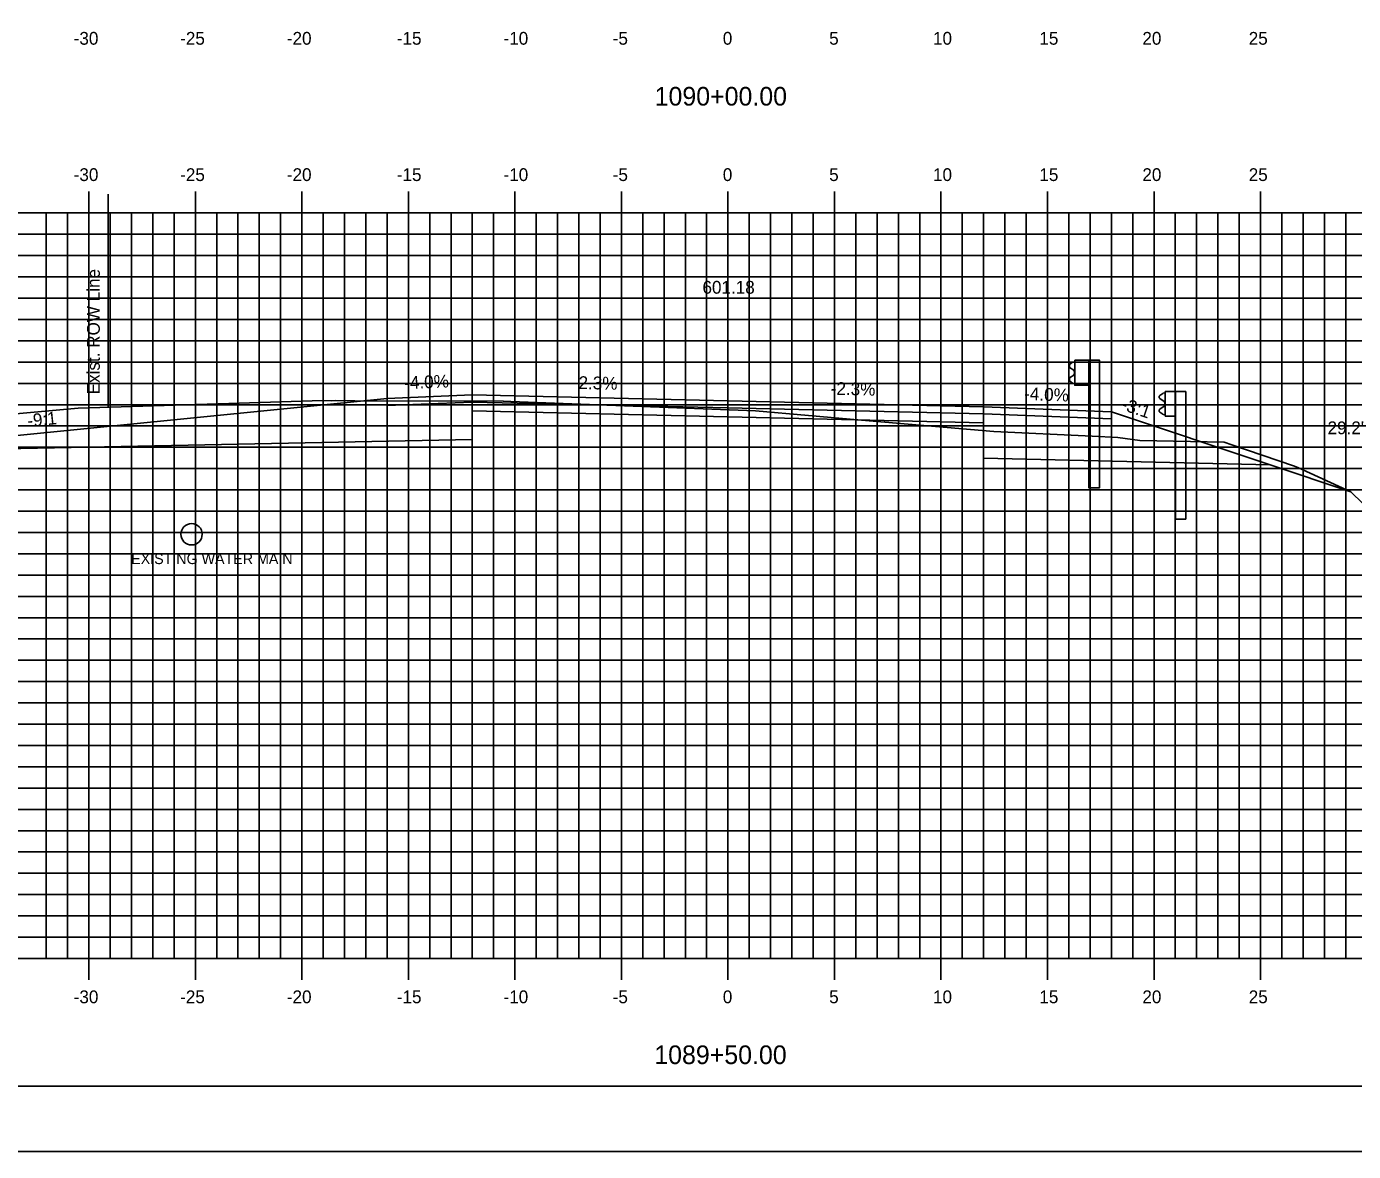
# Model space of a CAD drawing. Extents: x 1073421 to 1073591, y 779716 to 779826.
# Drawn here: x 1073471 to 1073533.3, y 779715.6 to 779768.5 of the extents above; entities that cross this region are included whole.
import ezdxf

# ---------------------------------------------------------------- set-up
doc = ezdxf.new("R2010")
doc.units = 0
for name, color, linetype in [('ANNOTATION', 7, 'Continuous'), ('BORDER', 7, 'Continuous'), ('D_Guardrail_Beam_Rt', 7, 'Continuous'), ('D_Roadway_Centerline', 7, 'Continuous'), ('D_Roadway_Centerline_Text', 7, 'Continuous'), ('D_Roadway_Edge_Pavement', 7, 'Continuous'), ('D_Roadway_Edge_Shoulder', 7, 'Continuous'), ('D_Roadway_Pavement', 7, 'Continuous'), ('D_Roadway_SlopeLines', 7, 'Continuous'), ('D_Roadway_SubGrade', 7, 'Continuous'), ('D_Text_Monospaced', 7, 'Continuous'), ('D_Text_Standard', 7, 'Continuous'), ('E_ROW_Line', 7, 'Continuous'), ('Existing Water Main', 7, 'Continuous'), ('H_V ANNOTATION', 7, 'Continuous'), ('M_Guardrail', 7, 'Continuous'), ('MAJOR', 7, 'Continuous'), ('MINOR', 7, 'Continuous'), ('PLOT BOUNDARY', 7, 'Continuous'), ('S_Guardrail_Beam', 7, 'Continuous'), ('S_Roadway_Centerline', 7, 'Continuous')]:
    doc.layers.add(name, color=color, linetype=linetype)

msp = doc.modelspace()

# ---------------------------------------------------------------- linework, layer by layer
at = {"layer": 'BORDER'}
msp.add_lwpolyline([(1073428.959, 779718.706), (1073588.959, 779718.706), (1073588.959, 779823.706), (1073428.959, 779823.706)], close=True, dxfattribs=at)
at = {"layer": 'D_Guardrail_Beam_Rt'}
msp.add_lwpolyline([(1073520.238, 779752.721), (1073520.156, 779752.706), (1073520.139, 779752.699), (1073519.996, 779752.599), (1073519.996, 779752.456), (1073520.191, 779752.319), (1073520.225, 779752.255), (1073520.225, 779752.164), (1073520.191, 779752.099), (1073519.996, 779751.963), (1073519.996, 779751.819), (1073520.139, 779751.719), (1073520.156, 779751.712), (1073520.238, 779751.698)], dxfattribs=at)
for points in [[(1073520.238, 779752.8), (1073520.904, 779752.8), (1073520.904, 779751.619), (1073520.238, 779751.619)], [(1073520.904, 779752.8), (1073521.397, 779752.8), (1073521.397, 779746.796), (1073520.904, 779746.796)]]:
    msp.add_lwpolyline(points, close=True, dxfattribs=at)
at = {"layer": 'D_Roadway_Centerline'}
for points in [[(1073487.959, 779751.001), (1073491.959, 779751.161), (1073503.959, 779750.885), (1073515.959, 779750.609), (1073519.959, 779750.449), (1073521.959, 779750.369)], [(1073529.418, 779747.882), (1073533.205, 779746.62)]]:
    msp.add_lwpolyline(points, dxfattribs=at)
at = {"layer": 'D_Roadway_Edge_Pavement'}
msp.add_lwpolyline([(1073491.959, 779750.827), (1073491.959, 779751.161), (1073503.959, 779750.885), (1073515.959, 779750.609), (1073515.959, 779750.275), (1073503.959, 779750.551)], close=True, dxfattribs=at)
at = {"layer": 'D_Roadway_Edge_Shoulder'}
msp.add_lwpolyline([(1073491.959, 779751.161), (1073487.959, 779751.001), (1073487.959, 779750.667), (1073491.959, 779750.827)], close=True, dxfattribs=at)
msp.add_lwpolyline([(1073515.959, 779750.609), (1073519.959, 779750.449), (1073521.959, 779750.369), (1073521.959, 779750.035), (1073515.959, 779750.275), (1073515.959, 779750.609)], dxfattribs=at)
at = {"layer": 'D_Roadway_Pavement'}
msp.add_lwpolyline([(1073491.959, 779750.411), (1073491.959, 779750.827), (1073503.959, 779750.551), (1073515.959, 779750.275), (1073515.959, 779749.859), (1073503.959, 779750.135)], close=True, dxfattribs=at)
msp.add_lwpolyline([(1073491.959, 779750.827), (1073491.959, 779750.411)], dxfattribs=at)
at = {"layer": 'D_Roadway_SlopeLines'}
for points in [[(1073491.959, 779751.161), (1073487.959, 779751.001)], [(1073521.959, 779750.369), (1073529.418, 779747.882), (1073533.205, 779746.62)]]:
    msp.add_lwpolyline(points, dxfattribs=at)
at = {"layer": 'D_Roadway_SubGrade'}
msp.add_lwpolyline([(1073491.959, 779750.827), (1073487.959, 779750.667), (1073487.959, 779751.001), (1073462.918, 779748.496), (1073491.959, 779749.077), (1073491.959, 779750.827)], close=True, dxfattribs=at)
msp.add_lwpolyline([(1073529.418, 779747.882), (1073515.959, 779748.192), (1073515.959, 779748.775), (1073515.959, 779750.275), (1073515.959, 779750.275), (1073521.959, 779750.035), (1073521.959, 779750.369)], dxfattribs=at)
at = {"layer": 'E_ROW_Line'}
msp.add_line((1073474.873, 779750.592), (1073474.873, 779760.592), dxfattribs=at)
msp.add_line((1073474.873, 779750.592), (1073474.873, 779760.592), dxfattribs=at)
at = {"layer": 'Existing Water Main'}
msp.add_lwpolyline([(1073478.78, 779744.623), (1073478.779, 779744.623)], dxfattribs=at)
msp.add_circle((1073478.779, 779744.623), 0.501, dxfattribs=at)
at = {"layer": 'M_Guardrail'}
for p, q in [((1073524.967, 779751.331), (1073525.459, 779751.331)), ((1073525.459, 779751.331), (1073525.459, 779745.331)), ((1073524.967, 779745.331), (1073524.967, 779750.165)), ((1073524.967, 779745.331), (1073525.459, 779745.331))]:
    msp.add_line(p, q, dxfattribs=at)
at = {"layer": 'MAJOR'}
for p, q in [((1073473.959, 779760.708), (1073473.959, 779759.706)), ((1073478.959, 779760.708), (1073478.959, 779759.706)), ((1073483.959, 779760.708), (1073483.959, 779759.706)), ((1073488.959, 779760.708), (1073488.959, 779759.706)), ((1073493.959, 779760.708), (1073493.959, 779759.706)), ((1073498.959, 779760.708), (1073498.959, 779759.706)), ((1073503.959, 779760.708), (1073503.959, 779759.706)), ((1073508.959, 779760.708), (1073508.959, 779759.706)), ((1073513.959, 779760.708), (1073513.959, 779759.706)), ((1073518.959, 779760.708), (1073518.959, 779759.706)), ((1073523.959, 779760.708), (1073523.959, 779759.706)), ((1073528.959, 779760.708), (1073528.959, 779759.706)), ((1073433.959, 779759.706), (1073573.959, 779759.706)), ((1073433.959, 779759.706), (1073573.959, 779759.706)), ((1073473.959, 779724.706), (1073473.959, 779759.706)), ((1073478.959, 779724.706), (1073478.959, 779759.706)), ((1073483.959, 779724.706), (1073483.959, 779759.706)), ((1073488.959, 779724.706), (1073488.959, 779759.706)), ((1073493.959, 779724.706), (1073493.959, 779759.706)), ((1073498.959, 779724.706), (1073498.959, 779759.706)), ((1073503.959, 779724.706), (1073503.959, 779759.706)), ((1073508.959, 779724.706), (1073508.959, 779759.706)), ((1073513.959, 779724.706), (1073513.959, 779759.706)), ((1073518.959, 779724.706), (1073518.959, 779759.706)), ((1073523.959, 779724.706), (1073523.959, 779759.706)), ((1073528.959, 779724.706), (1073528.959, 779759.706)), ((1073433.959, 779754.706), (1073573.959, 779754.706)), ((1073433.959, 779749.706), (1073573.959, 779749.706)), ((1073433.959, 779744.706), (1073573.959, 779744.706)), ((1073433.959, 779739.706), (1073573.959, 779739.706)), ((1073433.959, 779734.706), (1073573.959, 779734.706)), ((1073433.959, 779729.706), (1073573.959, 779729.706)), ((1073433.959, 779724.706), (1073573.959, 779724.706)), ((1073433.959, 779724.706), (1073573.959, 779724.706)), ((1073473.959, 779723.704), (1073473.959, 779724.706)), ((1073478.959, 779723.704), (1073478.959, 779724.706)), ((1073483.959, 779723.704), (1073483.959, 779724.706)), ((1073488.959, 779723.704), (1073488.959, 779724.706)), ((1073493.959, 779723.704), (1073493.959, 779724.706)), ((1073498.959, 779723.704), (1073498.959, 779724.706)), ((1073503.959, 779723.704), (1073503.959, 779724.706)), ((1073508.959, 779723.704), (1073508.959, 779724.706)), ((1073513.959, 779723.704), (1073513.959, 779724.706)), ((1073518.959, 779723.704), (1073518.959, 779724.706)), ((1073523.959, 779723.704), (1073523.959, 779724.706)), ((1073528.959, 779723.704), (1073528.959, 779724.706))]:
    msp.add_line(p, q, dxfattribs=at)
at = {"layer": 'MINOR'}
for p, q in [((1073471.959, 779724.706), (1073471.959, 779759.706)), ((1073472.959, 779724.706), (1073472.959, 779759.706)), ((1073474.959, 779724.706), (1073474.959, 779759.706)), ((1073475.959, 779724.706), (1073475.959, 779759.706)), ((1073476.959, 779724.706), (1073476.959, 779759.706)), ((1073477.959, 779724.706), (1073477.959, 779759.706)), ((1073479.959, 779724.706), (1073479.959, 779759.706)), ((1073480.959, 779724.706), (1073480.959, 779759.706)), ((1073481.959, 779724.706), (1073481.959, 779759.706)), ((1073482.959, 779724.706), (1073482.959, 779759.706)), ((1073484.959, 779724.706), (1073484.959, 779759.706)), ((1073485.959, 779724.706), (1073485.959, 779759.706)), ((1073486.959, 779724.706), (1073486.959, 779759.706)), ((1073487.959, 779724.706), (1073487.959, 779759.706)), ((1073489.959, 779724.706), (1073489.959, 779759.706)), ((1073490.959, 779724.706), (1073490.959, 779759.706)), ((1073491.959, 779724.706), (1073491.959, 779759.706)), ((1073492.959, 779724.706), (1073492.959, 779759.706)), ((1073494.959, 779724.706), (1073494.959, 779759.706)), ((1073495.959, 779724.706), (1073495.959, 779759.706)), ((1073496.959, 779724.706), (1073496.959, 779759.706)), ((1073497.959, 779724.706), (1073497.959, 779759.706)), ((1073499.959, 779724.706), (1073499.959, 779759.706)), ((1073500.959, 779724.706), (1073500.959, 779759.706)), ((1073501.959, 779724.706), (1073501.959, 779759.706)), ((1073502.959, 779724.706), (1073502.959, 779759.706)), ((1073504.959, 779724.706), (1073504.959, 779759.706)), ((1073505.959, 779724.706), (1073505.959, 779759.706)), ((1073506.959, 779724.706), (1073506.959, 779759.706)), ((1073507.959, 779724.706), (1073507.959, 779759.706)), ((1073509.959, 779724.706), (1073509.959, 779759.706)), ((1073510.959, 779724.706), (1073510.959, 779759.706)), ((1073511.959, 779724.706), (1073511.959, 779759.706)), ((1073512.959, 779724.706), (1073512.959, 779759.706)), ((1073514.959, 779724.706), (1073514.959, 779759.706)), ((1073515.959, 779724.706), (1073515.959, 779759.706)), ((1073516.959, 779724.706), (1073516.959, 779759.706)), ((1073517.959, 779724.706), (1073517.959, 779759.706)), ((1073519.959, 779724.706), (1073519.959, 779759.706)), ((1073520.959, 779724.706), (1073520.959, 779759.706)), ((1073521.959, 779724.706), (1073521.959, 779759.706)), ((1073522.959, 779724.706), (1073522.959, 779759.706)), ((1073524.959, 779724.706), (1073524.959, 779759.706)), ((1073525.959, 779724.706), (1073525.959, 779759.706)), ((1073526.959, 779724.706), (1073526.959, 779759.706)), ((1073527.959, 779724.706), (1073527.959, 779759.706)), ((1073529.959, 779724.706), (1073529.959, 779759.706)), ((1073530.959, 779724.706), (1073530.959, 779759.706)), ((1073531.959, 779724.706), (1073531.959, 779759.706)), ((1073532.959, 779724.706), (1073532.959, 779759.706)), ((1073433.959, 779758.706), (1073573.959, 779758.706)), ((1073433.959, 779757.706), (1073573.959, 779757.706)), ((1073433.959, 779756.706), (1073573.959, 779756.706)), ((1073433.959, 779755.706), (1073573.959, 779755.706)), ((1073433.959, 779753.706), (1073573.959, 779753.706)), ((1073433.959, 779752.706), (1073573.959, 779752.706)), ((1073433.959, 779751.706), (1073573.959, 779751.706)), ((1073433.959, 779750.706), (1073573.959, 779750.706)), ((1073433.959, 779748.706), (1073573.959, 779748.706)), ((1073433.959, 779747.706), (1073573.959, 779747.706)), ((1073433.959, 779746.706), (1073573.959, 779746.706)), ((1073433.959, 779745.706), (1073573.959, 779745.706)), ((1073433.959, 779743.706), (1073573.959, 779743.706)), ((1073433.959, 779742.706), (1073573.959, 779742.706)), ((1073433.959, 779741.706), (1073573.959, 779741.706)), ((1073433.959, 779740.706), (1073573.959, 779740.706)), ((1073433.959, 779738.706), (1073573.959, 779738.706)), ((1073433.959, 779737.706), (1073573.959, 779737.706)), ((1073433.959, 779736.706), (1073573.959, 779736.706)), ((1073433.959, 779735.706), (1073573.959, 779735.706)), ((1073433.959, 779733.706), (1073573.959, 779733.706)), ((1073433.959, 779732.706), (1073573.959, 779732.706)), ((1073433.959, 779731.706), (1073573.959, 779731.706)), ((1073433.959, 779730.706), (1073573.959, 779730.706)), ((1073433.959, 779728.706), (1073573.959, 779728.706)), ((1073433.959, 779727.706), (1073573.959, 779727.706)), ((1073433.959, 779726.706), (1073573.959, 779726.706)), ((1073433.959, 779725.706), (1073573.959, 779725.706))]:
    msp.add_line(p, q, dxfattribs=at)
at = {"layer": 'PLOT BOUNDARY'}
msp.add_lwpolyline([(1073420.866, 779715.646), (1073590.866, 779715.646), (1073590.866, 779825.646), (1073420.866, 779825.646)], close=True, dxfattribs=at)
at = {"layer": 'S_Guardrail_Beam'}
for p, q in [((1073524.379, 779751.237), (1073524.235, 779751.137)), ((1073524.477, 779751.258), (1073524.395, 779751.244)), ((1073524.477, 779751.331), (1073524.967, 779751.331)), ((1073524.477, 779750.165), (1073524.477, 779751.331)), ((1073524.967, 779751.331), (1073524.967, 779750.165)), ((1073524.235, 779750.994), (1073524.431, 779750.858)), ((1073524.431, 779750.638), (1073524.235, 779750.502)), ((1073524.464, 779750.793), (1073524.464, 779750.702)), ((1073524.235, 779750.359), (1073524.379, 779750.259)), ((1073524.395, 779750.252), (1073524.477, 779750.237)), ((1073524.967, 779750.165), (1073524.477, 779750.165))]:
    msp.add_line(p, q, dxfattribs=at)
for centre, major_axis, start_param, end_param in [((1073524.285, 779751.066), (-0.0877, 0), 5.323254, 7.243116), ((1073524.403, 779751.203), (-0.0417, 0), 4.886922, 5.323254), ((1073524.285, 779750.43), (-0.0877, 0), 5.323254, 7.243116), ((1073524.385, 779750.793), (0.0789, 0), 0, 0.959931), ((1073524.385, 779750.702), (0.0789, 0), 5.323254, 6.283185), ((1073524.403, 779750.293), (-0.0417, 0), 0.959931, 1.396263)]:
    msp.add_ellipse(centre, major_axis=major_axis, ratio=0.995501, start_param=start_param, end_param=end_param, dxfattribs=at)
at = {"layer": 'S_Roadway_Centerline'}
msp.add_lwpolyline([(1073469.477, 779750.176), (1073473.454, 779750.55), (1073480.535, 779750.758), (1073484.922, 779750.898), (1073485.349, 779750.892), (1073485.537, 779750.896), (1073486.449, 779750.884), (1073493.413, 779750.869), (1073493.419, 779750.869), (1073493.761, 779750.848), (1073505.247, 779750.42), (1073510.236, 779749.978), (1073516.448, 779749.443), (1073521.061, 779749.233), (1073522.257, 779749.171), (1073523.287, 779749.026), (1073527.245, 779748.943), (1073527.608, 779748.824), (1073530.502, 779747.834), (1073530.706, 779747.759), (1073533.204, 779746.621), (1073537.063, 779742.86)], dxfattribs=at)

# ---------------------------------------------------------------- texts
at = {"layer": 'ANNOTATION'}
for s, rotation, p in [('-4.0%', 2.29061, (1073488.775, 779751.434)), ('2.3%', 358.68243, (1073496.939, 779751.446)), ('-2.3%', 358.68243, (1073508.779, 779751.174)), ('-4.0%', 357.70939, (1073517.855, 779750.934)), ('-3:1', 341.56505, (1073522.365, 779750.489)), ('-9:1', 5.9837, (1073471.101, 779749.651))]:
    msp.add_text(s, height=0.6, rotation=rotation, dxfattribs=at).set_placement(p)
at = {"layer": 'D_Roadway_Centerline_Text'}
msp.add_text('601.18', height=0.6, dxfattribs=at).set_placement((1073502.763, 779755.917))
at = {"layer": 'D_Text_Monospaced'}
msp.add_text('EXISTING WATER MAIN', height=0.49998, dxfattribs=at).set_placement((1073475.946, 779743.223))
at = {"layer": 'D_Text_Standard'}
msp.add_text("29.2'", height=0.6, dxfattribs=at).set_placement((1073532.106, 779749.32))
at = {"layer": 'E_ROW_Line'}
msp.add_text('Exist. ROW Line', height=0.6, rotation=90, dxfattribs=at).set_placement((1073474.473, 779751.192))
at = {"layer": 'H_V ANNOTATION'}
for s, height, p in [('-30', 0.6, (1073473.247, 779767.606)), ('-25', 0.6, (1073478.245, 779767.606)), ('-20', 0.6, (1073483.253, 779767.606)), ('-15', 0.6, (1073488.416, 779767.606)), ('-10', 0.6, (1073493.424, 779767.606)), ('-5', 0.6, (1073498.55, 779767.606)), ('0', 0.6, (1073503.718, 779767.606)), ('5', 0.6, (1073508.71, 779767.606)), ('10', 0.6, (1073513.585, 779767.606)), ('15', 0.6, (1073518.577, 779767.606)), ('20', 0.6, (1073523.413, 779767.606)), ('25', 0.6, (1073528.405, 779767.606)), ('1090+00.00', 0.875, (1073500.518, 779764.749)), ('-30', 0.6, (1073473.247, 779761.206)), ('-25', 0.6, (1073478.245, 779761.206)), ('-20', 0.6, (1073483.253, 779761.206)), ('-15', 0.6, (1073488.416, 779761.206)), ('-10', 0.6, (1073493.424, 779761.206)), ('-5', 0.6, (1073498.55, 779761.206)), ('0', 0.6, (1073503.718, 779761.206)), ('5', 0.6, (1073508.71, 779761.206)), ('10', 0.6, (1073513.585, 779761.206)), ('15', 0.6, (1073518.577, 779761.206)), ('20', 0.6, (1073523.413, 779761.206)), ('25', 0.6, (1073528.405, 779761.206)), ('-30', 0.6, (1073473.247, 779722.606)), ('-25', 0.6, (1073478.245, 779722.606)), ('-20', 0.6, (1073483.253, 779722.606)), ('-15', 0.6, (1073488.416, 779722.606)), ('-10', 0.6, (1073493.424, 779722.606)), ('-5', 0.6, (1073498.55, 779722.606)), ('0', 0.6, (1073503.718, 779722.606)), ('5', 0.6, (1073508.71, 779722.606)), ('10', 0.6, (1073513.585, 779722.606)), ('15', 0.6, (1073518.577, 779722.606)), ('20', 0.6, (1073523.413, 779722.606)), ('25', 0.6, (1073528.405, 779722.606)), ('1089+50.00', 0.875, (1073500.502, 779719.749))]:
    msp.add_text(s, height=height, dxfattribs=at).set_placement(p)

doc.saveas('drawing.dxf')
